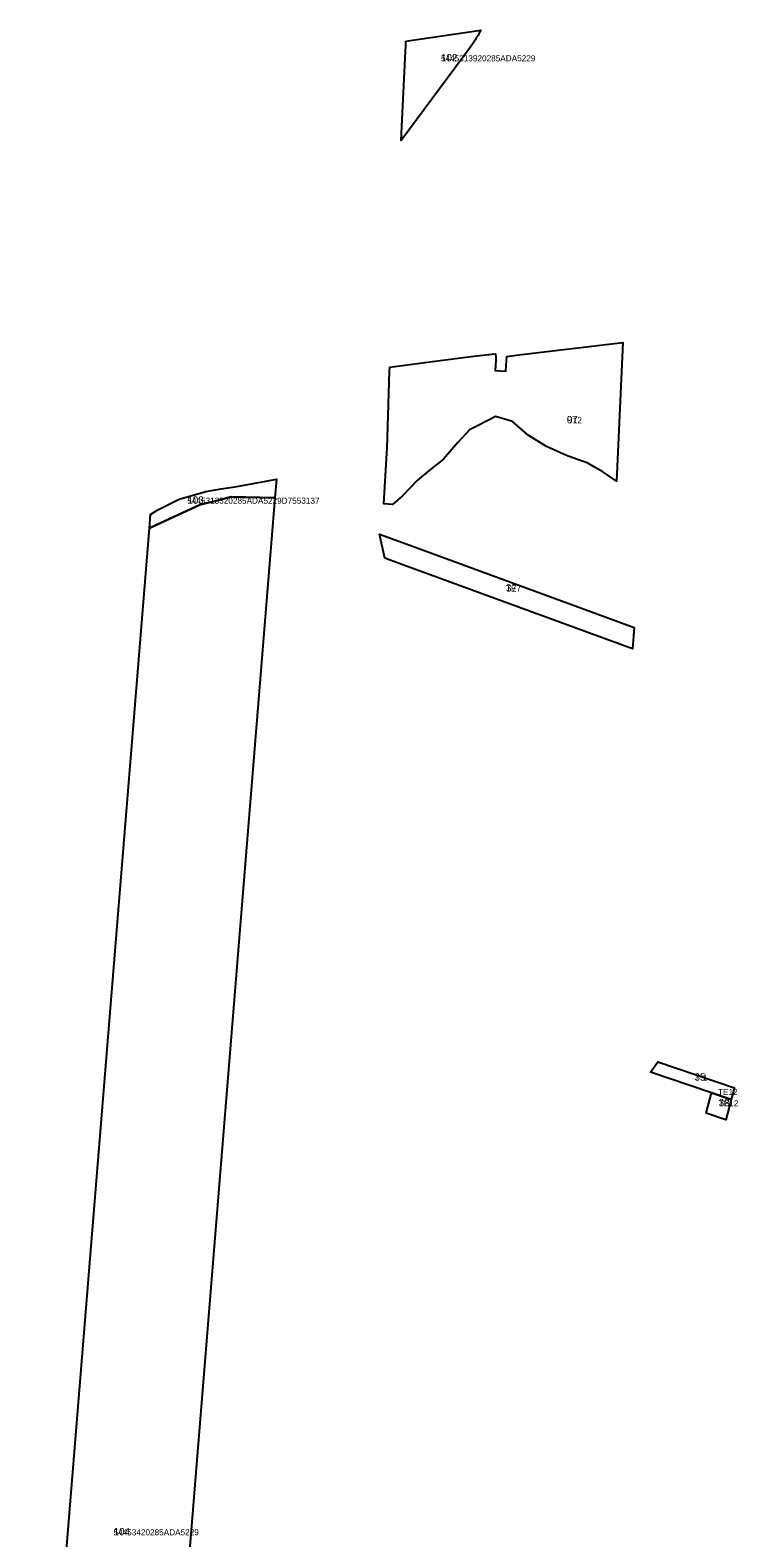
# Model space of a CAD drawing. Extents: x -545623 to -541713, y -1153152 to -1149975.
# Drawn here: x -544842 to -544265, y -1151876 to -1150647 of the extents above; entities that cross this region are included whole.
import ezdxf

# ---------------------------------------------------------------- set-up
doc = ezdxf.new("R2010")
doc.units = 0
for name, color, linetype in [('96120023', 7, 'Continuous'), ('96140023', 7, 'Continuous'), ('ID_VPO', 7, 'Continuous'), ('ID_VPS', 7, 'Continuous')]:
    doc.layers.add(name, color=color, linetype=linetype)

msp = doc.modelspace()

# ---------------------------------------------------------------- linework, layer by layer
at = {"layer": '96120023'}
for points in [[(-544535.7, -1150656.1), (-544474.5, -1150647.1), (-544474.9, -1150647.7), (-544475.4, -1150648.7), (-544475.9, -1150649.6), (-544476.4, -1150650.5), (-544476.9, -1150651.5), (-544477.5, -1150652.4), (-544478, -1150653.3), (-544478.6, -1150654.2), (-544479.1, -1150655.1), (-544479.7, -1150656), (-544480.3, -1150656.9), (-544480.9, -1150657.8), (-544481.5, -1150658.6), (-544482.1, -1150659.5), (-544482.7, -1150660.4), (-544483.3, -1150661.2), (-544539.6, -1150736.9), (-544538.8, -1150719.8), (-544535.8, -1150659.1)], [(-544646.8, -1151014.1), (-544641.2, -1151013.1), (-544642.4, -1151028.2), (-544678.1, -1151027.5), (-544687.1, -1151029.8), (-544703.7, -1151034), (-544738.9, -1151050.3), (-544744.7, -1151053), (-544743.9, -1151042), (-544737.9, -1151038), (-544737.8, -1151038), (-544720.5, -1151029.5), (-544698.8, -1151023), (-544686.4, -1151021), (-544673.4, -1151019)], [(-544398.4, -1151134.1), (-544541.3, -1151081.8), (-544552.9, -1151077.5), (-544557.2, -1151057.9), (-544535.5, -1151065.8), (-544535.5, -1151065.8), (-544392.6, -1151118.1), (-544349.5, -1151133.9), (-544351.1, -1151151.4)], [(-544270.5, -1151518.8), (-544336.3, -1151496.5), (-544330.2, -1151488), (-544267.9, -1151509.1), (-544268.4, -1151510.8)], [(-544270.5, -1151518.8), (-544274.8, -1151535.3), (-544291, -1151529.8), (-544286.6, -1151513.3)], [(-544270.5, -1151518.8), (-544286.6, -1151513.3), (-544286.6, -1151513.3)]]:
    msp.add_lwpolyline(points, close=True, dxfattribs=at)
msp.add_lwpolyline([(-544842, -1152250.7), (-544744.7, -1151053), (-544738.9, -1151050.3), (-544703.7, -1151034), (-544687.1, -1151029.8), (-544678.1, -1151027.5), (-544642.4, -1151028.2), (-544742.3, -1152258.6)], dxfattribs=at)
at = {"layer": '96140023'}
for points in [[(-544443.5, -1150911.6), (-544358.9, -1150901.6), (-544364.1, -1151014.6), (-544375.1, -1151007), (-544381.4, -1151003.5), (-544388, -1150999.7), (-544399.7, -1150995.6), (-544404.8, -1150993.9), (-544421, -1150986.5), (-544436, -1150977.3), (-544448.8, -1150966.1), (-544462.6, -1150961.9), (-544465.6, -1150963.5), (-544481.7, -1150971.8), (-544483.3, -1150972.6), (-544483.6, -1150972.7), (-544493.4, -1150983.2), (-544505.1, -1150996.8), (-544515, -1151004.7), (-544526.3, -1151013.8), (-544538.5, -1151026.7), (-544546.7, -1151033.6), (-544553.6, -1151033.1), (-544551.1, -1150991.8), (-544550.9, -1150988.1), (-544550.9, -1150987.7), (-544549, -1150925), (-544548.9, -1150921.7), (-544524.4, -1150918.5), (-544495.3, -1150914.6), (-544480.2, -1150912.9), (-544465.7, -1150911.3), (-544462.7, -1150910.9), (-544462.3, -1150914.1), (-544462.4, -1150916.1), (-544462.9, -1150924.5), (-544454.2, -1150925.1), (-544453.7, -1150916.4), (-544453.5, -1150913)], [(-544642.4, -1151028.2), (-544678.1, -1151027.5), (-544687.1, -1151029.8), (-544703.7, -1151034), (-544738.9, -1151050.3), (-544744.7, -1151053), (-544743.9, -1151042), (-544737.9, -1151038), (-544737.8, -1151038), (-544720.5, -1151029.5), (-544698.8, -1151023), (-544686.4, -1151021), (-544673.4, -1151019), (-544646.8, -1151014.1), (-544641.2, -1151013.1)]]:
    msp.add_lwpolyline(points, close=True, dxfattribs=at)

# ---------------------------------------------------------------- texts
at = {"layer": '96120023'}
for s, rotation, p in [('5445313920285ADA5229', 360, (-544507.1, -1150672.5)), ('5445313320285ADA5229D7553137', 0, (-544713.9, -1151033.1)), ('TE7', 0, (-544454.1, -1151104.7)), ('T*1', 0, (-544300.4, -1151503.4)), ('TE12', 360, (-544281.3, -1151515.1)), ('TE12', 360, (-544280.7, -1151524.3)), ('54453420285ADA5229', 360, (-544774, -1151874))]:
    msp.add_text(s, height=5, rotation=rotation, dxfattribs=at).set_placement(p)
at = {"layer": '96140023'}
for s, rotation, p in [('U12', 360, (-544404.5, -1150967.6)), ('5445313320285ADA5229D7553137', 0, (-544713.9, -1151033.1))]:
    msp.add_text(s, height=5, rotation=rotation, dxfattribs=at).set_placement(p)
at = {"layer": 'ID_VPO'}
for s, rotation, p in [('97', 360, (-544404.5, -1150967.6)), ('103', 0, (-544713.9, -1151033.1))]:
    msp.add_text(s, height=6, rotation=rotation, dxfattribs=at).set_placement(p)
at = {"layer": 'ID_VPS'}
for s, rotation, p in [('102', 360, (-544507.1, -1150672.5)), ('103', 0, (-544713.9, -1151033.1)), ('37', 360, (-544454.1, -1151104.7)), ('35', 0, (-544300.4, -1151503.4)), ('38', 0, (-544280.7, -1151524.3)), ('104', 360, (-544774, -1151874))]:
    msp.add_text(s, height=6, rotation=rotation, dxfattribs=at).set_placement(p)

doc.saveas('drawing.dxf')
